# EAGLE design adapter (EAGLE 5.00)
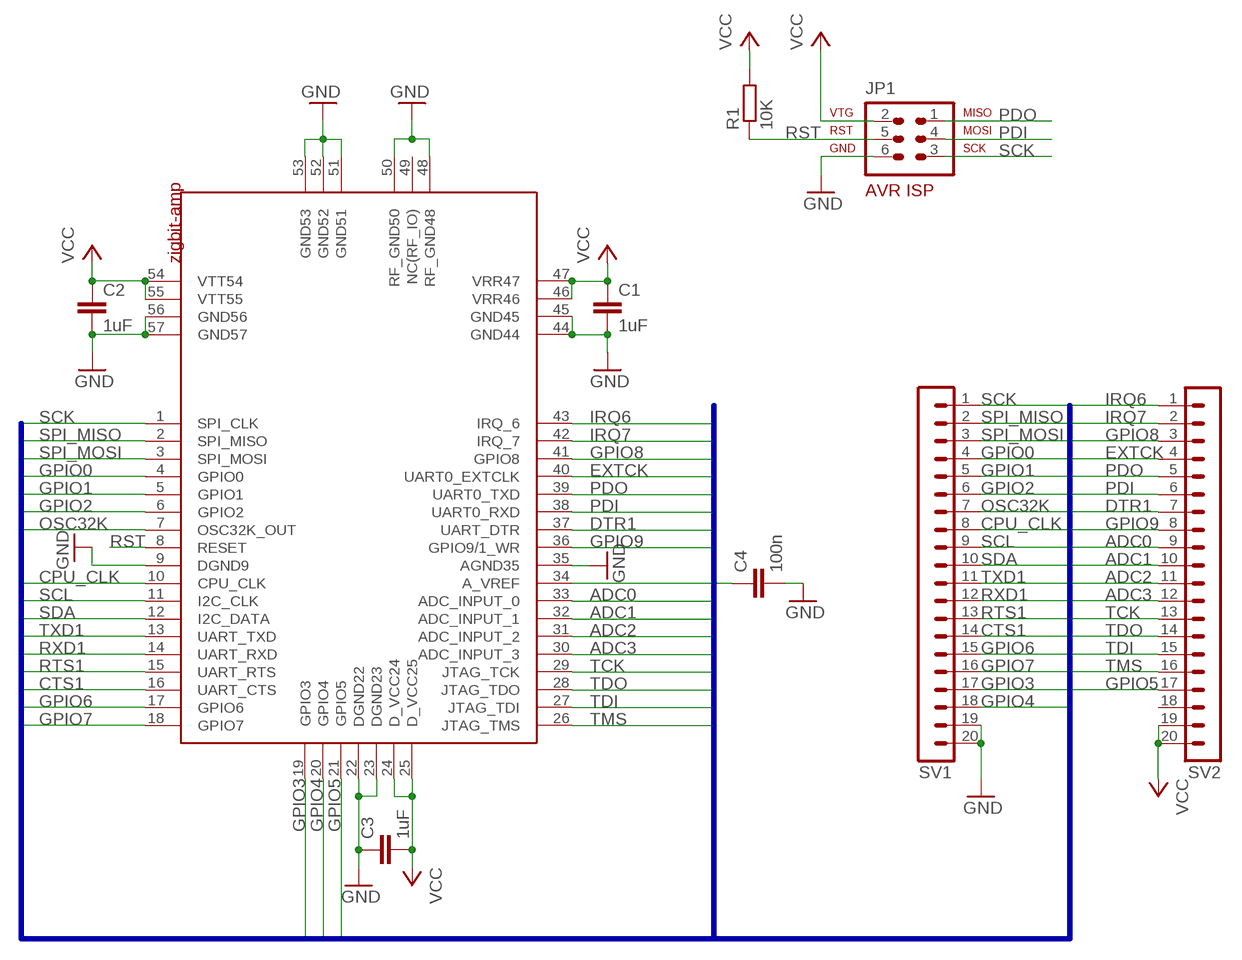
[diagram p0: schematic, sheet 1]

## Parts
C1  1uF  C-EUC1206  [C1206]
C2  1uF  C-EUC1206  [C1206]
C3  1uF  C-EUC1206  [C1206]
C4  100n  C-EUC0603  [C0603]
JP1  AVR-ISP-6  [AVR-ISP-6]
R1  10K  R-EU_R0603  [R0603]
SV1  MA20-1L  [MA20-1L]
SV2  MA20-1L  [MA20-1L]
U$1  ZIGBIT-AMP  [BOARD]

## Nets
ADC0: SV2.9 U$1.33(ADC_INPUT_0)
ADC1: SV2.10 U$1.32(ADC_INPUT_1)
ADC2: SV2.11 U$1.31(ADC_INPUT_2)
ADC3: SV2.12 U$1.30(ADC_INPUT_3)
CPU_CLK: SV1.8 U$1.10(CPU_CLK)
CTS1: SV1.14 U$1.16(UART_CTS)
DTR1: SV2.7 U$1.37(UART_DTR)
EXTCK: SV2.4 U$1.40(UART0_EXTCLK)
GND: C1.2 C2.2 C3.1 C4.2 JP1.6 SV1.19 SV1.20 U$1.9(DGND9) U$1.22(DGND22) U$1.23(DGND23) U$1.35(AGND35) U$1.44(GND44) U$1.45(GND45) U$1.48(RF_GND48) U$1.50(RF_GND50) U$1.51(GND51) U$1.52(GND52) U$1.53(GND53) U$1.56(GND56) U$1.57(GND57)
GPIO0: SV1.4 U$1.4(GPIO0)
GPIO1: SV1.5 U$1.5(GPIO1)
GPIO2: SV1.6 U$1.6(GPIO2)
GPIO3: SV1.17 U$1.19(GPIO3)
GPIO4: SV1.18 U$1.20(GPIO4)
GPIO5: SV2.17 U$1.21(GPIO5)
GPIO6: SV1.15 U$1.17(GPIO6)
GPIO7: SV1.16 U$1.18(GPIO7)
GPIO8: SV2.3 U$1.41(GPIO8)
GPIO9: SV2.8 U$1.36(GPIO9/1_WR)
IRQ6: SV2.1 U$1.43(IRQ_6)
IRQ7: SV2.2 U$1.42(IRQ_7)
N$7: C4.1 U$1.34(A_VREF)
OSC32K: SV1.7 U$1.7(OSC32K_OUT)
PDI: JP1.4 SV2.6 U$1.38(UART0_RXD)
PDO: JP1.1 SV2.5 U$1.39(UART0_TXD)
RST: JP1.5 R1.1 U$1.8(RESET)
RTS1: SV1.13 U$1.15(UART_RTS)
RXD1: SV1.12 U$1.14(UART_RXD)
SCK: JP1.3 SV1.1 U$1.1(SPI_CLK)
SCL: SV1.9 U$1.11(I2C_CLK)
SDA: SV1.10 U$1.12(I2C_DATA)
SPI_MISO: SV1.2 U$1.2(SPI_MISO)
SPI_MOSI: SV1.3 U$1.3(SPI_MOSI)
TCK: SV2.13 U$1.29(JTAG_TCK)
TDI: SV2.15 U$1.27(JTAG_TDI)
TDO: SV2.14 U$1.28(JTAG_TDO)
TMS: SV2.16 U$1.26(JTAG_TMS)
TXD1: SV1.11 U$1.13(UART_TXD)
VCC: C1.1 C2.1 C3.2 JP1.2 R1.2 SV2.19 SV2.20 U$1.24(D_VCC24) U$1.25(D_VCC25) U$1.46(VRR46) U$1.47(VRR47) U$1.54(VTT54) U$1.55(VTT55)
Unconnected: SV2.18 U$1.49(NC(RF_IO))

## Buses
SCK,SPI_MISO,SPI_MOSI,GPIO0,GPIO1,GPIO2,GPIO3,GPIO4,GPIO5,GPIO6,GPIO7,GPIO8,OSC32K,CPU_CLK,SCL,SDA,TXD1,RXD1,RTS1,CTS1,TMS,TDO,TDI,TCK,ADC3,ADC2,ADC1,ADC0,GPIO9,DTR1,MISO,MOSI,EXTCK,IRQ6,IRQ7

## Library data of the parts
C1-C4 = rcl:C-EU: CAPACITOR, European symbol
JP1 = dan:AVR-ISP-6: AVR ISP-6 Serial Programming Header
R1 = rcl:R-EU_: RESISTOR, European symbol
SV1 SV2 = con-lstb:MA20-1L: PIN HEADER
U$1 = zigbit:ZIGBIT-AMP: ZigBitTM Amp OEM Modules - ZDM-A1281-PN/PN0 (MNZB-A24-UFL/U0)

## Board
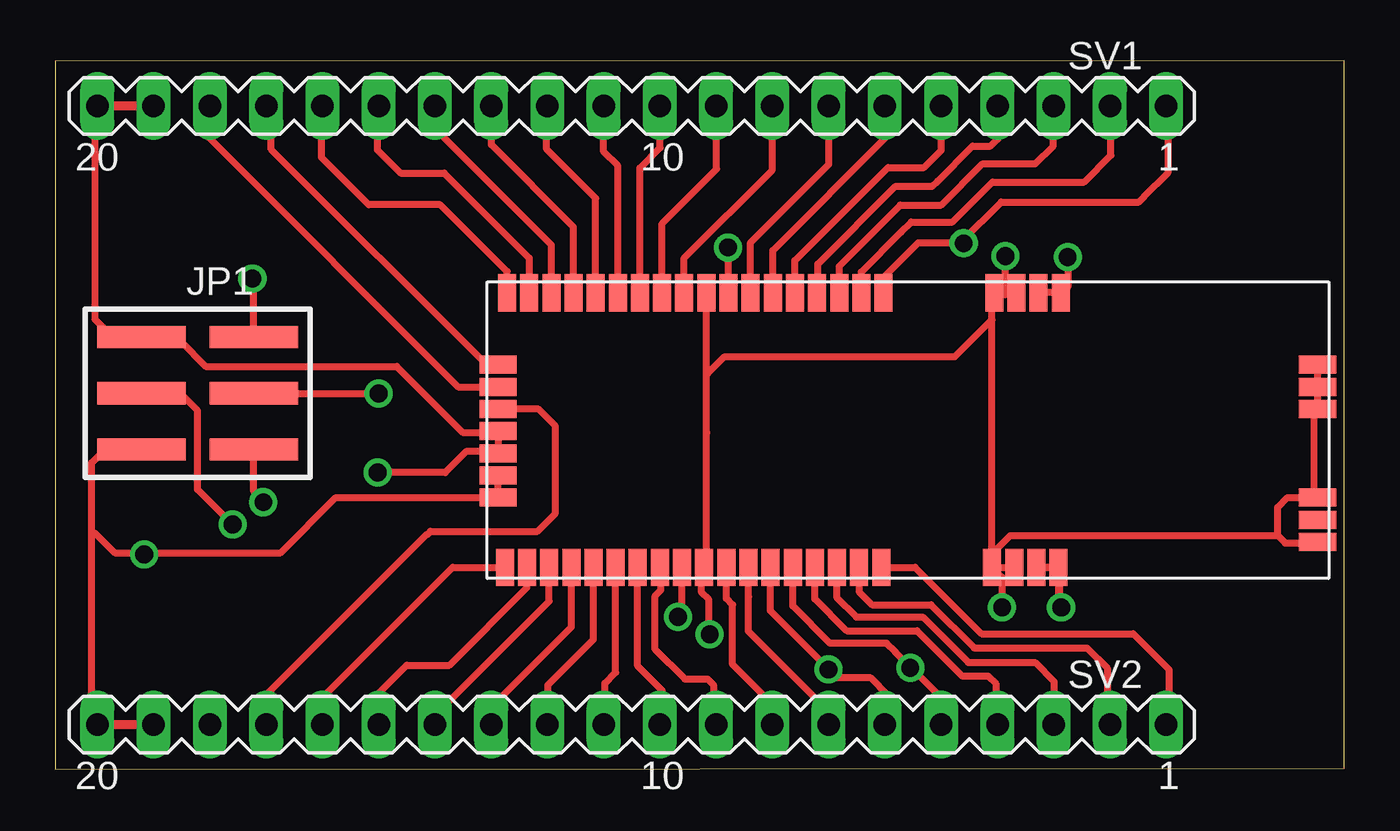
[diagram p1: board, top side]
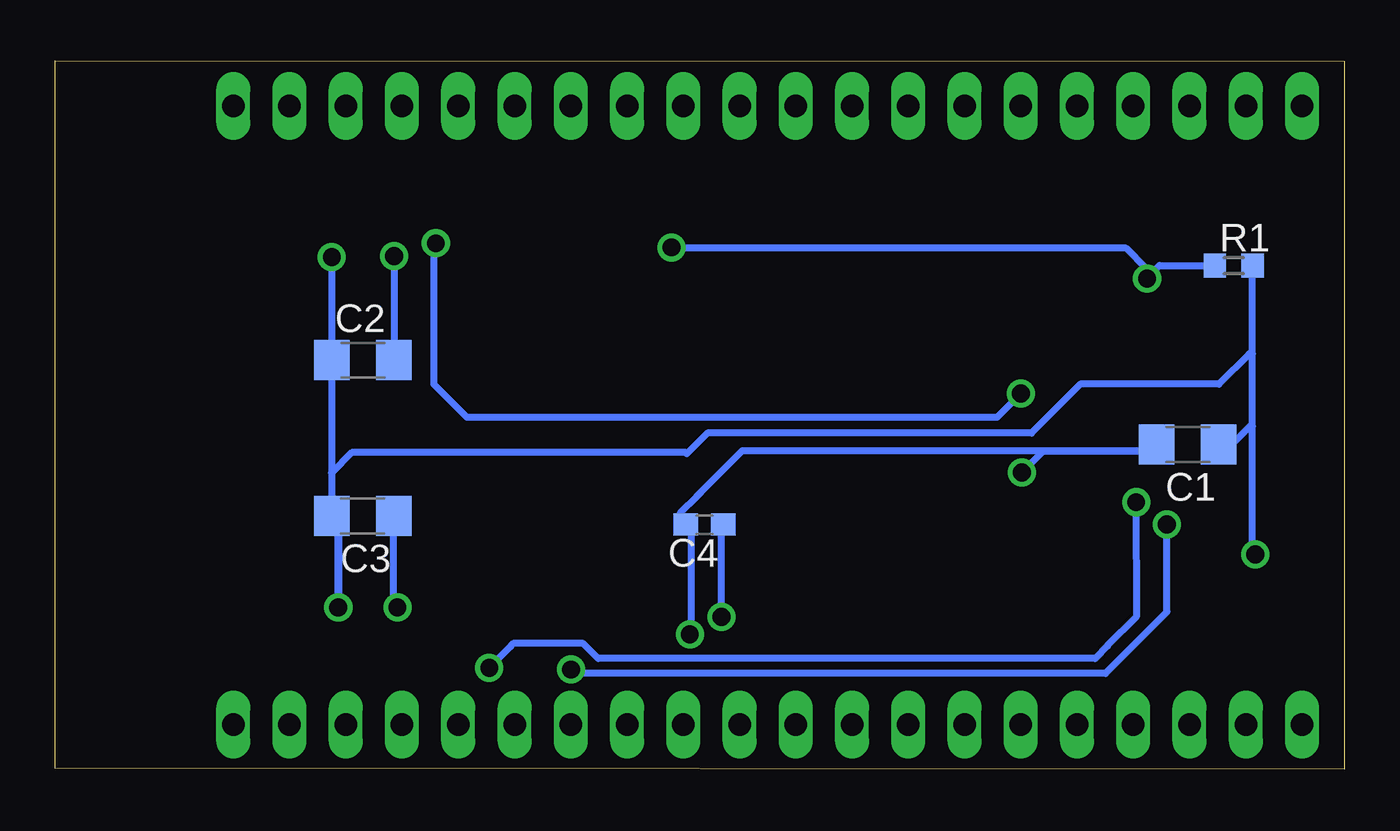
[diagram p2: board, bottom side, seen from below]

Size 58.2 x 32 mm. Coordinates in mm from the lower left corner, seen from the top.
Outline: 0,0 58.2,0.04 58.2,32 0,31.96 0,0
Copper layers (1*16): Top 0.035mm / dielectric 1.5mm / Bottom 0.035mm
Design rules "default": minimum track width 10mil, minimum drill 24mil, track to track 8mil, track to pad 8mil, pad to pad 8mil, via to via 8mil, smd to smd 8mil, copper to edge 40mil, drill to drill 8mil, minimum pad ring 10mil, minimum via ring 8mil, stop-mask expansion 4mil, vias tented up to drill 0mil, thermal gap 10mil

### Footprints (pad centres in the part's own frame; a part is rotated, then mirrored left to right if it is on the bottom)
C1206 = smd 1.6 x 1.8: 1 -1.4,0; 2 1.4,0
C0603 = smd 1.1 x 1: 1 -0.85,0; 2 0.85,0
AVR-ISP-6 = smd 1 x 4: 1 -2.54,-2.54; 2 -2.54,2.54; 3 0,-2.54; 4 0,2.54; 5 2.54,-2.54; 6 2.54,2.54
R0603 = smd 1 x 1.1: 1 -0.85,0; 2 0.85,0
MA20-1L = drill 1.016 long: 1 24.13,0; 2 21.59,0; 3 19.05,0; 4 16.51,0; 5 13.97,0; 6 11.43,0; 7 8.89,0; 8 6.35,0; 9 3.81,0; 10 1.27,0; 11 -1.27,0; 12 -3.81,0; 13 -6.35,0; 14 -8.89,0; 15 -11.43,0; 16 -13.97,0; 17 -16.51,0; 18 -19.05,0; 19 -21.59,0; 20 -24.13,0
BOARD = smd 0.813 x 1.676: 1 17.9,-0.5; 2 16.9,-0.5; 3 15.9,-0.5; 4 14.9,-0.5; 5 13.9,-0.5; 6 12.9,-0.5; 7 11.9,-0.5; 8 10.9,-0.5; 9 9.9,-0.5; 10 8.9,-0.5; 11 7.9,-0.5; 12 6.9,-0.5; 13 5.9,-0.5; 14 4.9,-0.5; 15 3.9,-0.5; 16 2.9,-0.5; 17 1.9,-0.5; 18 0.9,-0.5; 26 0.8,-12.9; 27 1.8,-12.9; 28 2.8,-12.9; 29 3.8,-12.9; 30 4.8,-12.9; 31 5.8,-12.9; 32 6.8,-12.9; 33 7.8,-12.9; 34 8.8,-12.9; 35 9.8,-12.9; 36 10.8,-12.9; 37 11.8,-12.9; 38 12.8,-12.9; 39 13.8,-12.9; 40 14.8,-12.9; 41 15.8,-12.9; 42 16.8,-12.9; 43 17.8,-12.9; 44 22.8,-12.9; 45 23.8,-12.9; 46 24.8,-12.9; 47 25.8,-12.9; 54 25.9,-0.5; 55 24.9,-0.5; 56 23.9,-0.5; 57 22.9,-0.5 | smd 1.676 x 0.813: 19 0.5,-3.75; 20 0.5,-4.75; 21 0.5,-5.75; 22 0.5,-6.75; 23 0.5,-7.75; 24 0.5,-8.75; 25 0.5,-9.75; 48 37.5,-11.75; 49 37.5,-10.75; 50 37.5,-9.75; 51 37.5,-5.75; 52 37.5,-4.75; 53 37.5,-3.75

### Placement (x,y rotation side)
C1  7.06,14.66 180 bottom
C2  44.3,18.47 0 bottom
C3  44.32,11.43 180 bottom
C4  28.89,11.05 180 bottom
JP1  6.42,16.98 90 top
R1  4.99,22.74 0 bottom
SV1  26.03,29.95 0 top
SV2  26.03,2.01 0 top
U$1  19.5,22.01 0 top

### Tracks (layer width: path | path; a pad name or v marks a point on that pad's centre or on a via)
ADC0
  Top 0.305: SV2.9 29.84,2.4 29.86,2.42 29.73,2.55 29.73,3.77 29.74,3.78 29.45,4.07 28.42,4.07 27.09,5.4 27.09,7.82 27.34,8.08 27.34,8.99 27.3,9.04 U$1.33
ADC1
  Top 0.305: U$1.32 26.3,4.65 27.41,3.54 27.41,2.13 SV2.10
ADC2
  Top 0.305: U$1.31 25.3,4.36 24.81,3.88 24.81,2.18 24.76,2.13 SV2.11
ADC3
  Top 0.305: U$1.30 24.3,5.86 22.24,3.8 22.24,2.26 22.11,2.13 SV2.12
CPU_CLK
  Top 0.305: U$1.10 28.4,23.08 32.38,27.06 32.38,30.09 | 32.38,30.09 SV1.8 | 32.38,30.09 32.22,30.24
CTS1
  Top 0.305: U$1.16 22.4,23.67 17.32,28.74 17.32,29.99 17.14,30.17 | 17.14,30.17 17.12,30.2 | 17.14,30.17 SV1.14
DTR1
  Top 0.305: 31.3,7.79 U$1.37 | 31.3,7.79 31.3,7.75 | SV2.7 34.92,2.03 34.95,2.06 34.92,2.1 34.92,2.6 31.29,6.23 31.29,7.77 31.31,7.79 31.3,7.79
EXTCK
  Top 0.305: U$1.40 34.3,7.68 35.73,6.25 38.91,6.25 40.95,4.21 42.12,4.21 42.46,3.86 42.46,2.33 42.57,2.22 42.54,2.19 SV2.4
GND  (via drill 0.8 pad 1.27)
  Top 0.305: SV1.19 1.85,29.95 1.8,30.01 1.8,20.31 2.72,19.38 3.93,19.38 | 3.93,19.38 3.88,19.43 JP1.6 | 3.93,19.38 3.97,19.34 5.64,19.34 6.8,18.19 15.41,18.19 18.39,15.21 19.77,15.21 19.83,15.14 19.96,15.26 U$1.22 U$1.23 | U$1.23 20.1,14.17 | U$1.23 | U$1.52 57,17.04 56.94,16.98 | U$1.52 U$1.53 | 57,16.14 U$1.51 | 57,16.14 U$1.52 | 57,16.14 56.84,15.98 56.84,12.4 56.78,12.34 56.86,12.26 U$1.50 55.64,12.26 55.2,11.82 55.2,10.54 | 55.2,10.54 55.53,10.21 56.6,10.21 56.64,10.18 56.72,10.26 U$1.48 | 42.3,9.36 42.27,9.38 | U$1.44 42.3,9.36 | U$1.45 42.55,9.11 42.3,9.36 | 42.29,21.51 U$1.57 | U$1.57 42.9,21.51 | 42.9,21.51 U$1.56 | 42.29,21.51 42.26,21.54 | 29.19,9.54 29.3,9.43 U$1.35 | 29.4,15.24 29.4,9.75 29.19,9.54 | 29.4,15.24 29.4,17.86 | 29.4,17.86 U$1.9 | 29.4,15.24 29.41,15.16 | 42.29,21.51 42.29,20.3 40.62,18.63 30.23,18.63 29.45,17.86 29.4,17.86 | 55.2,10.54 43.13,10.54 42.27,9.69 | U$1.44 42.35,9.16 42.27,9.24 42.27,9.69 | U$1.57 42.4,21.32 42.27,21.2 42.27,9.69 | 29.19,9.54 29.19,7.97 29.5,7.65 29.5,6.17 29.57,6.1 v29.55,6.08 | U$1.44 42.75,8.66 v42.75,7.3 | 42.9,21.51 42.9,21.42 | 42.9,21.51 v42.9,23.17 | v14.56,13.39 17.6,13.39 18.54,14.33 19.92,14.33 U$1.23 | U$1.23 20.01,14.24
  Top 0.406: SV1.20 2.12,29.95 2.13,29.94 2.14,29.95 SV1.19
  Bottom 0.305: v29.55,6.08 29.55,6.06 29.52,6.03 29.49,6.06 29.49,10.88 29.7,11.08 C4.2 29.86,11.05 29.91,10.99 29.98,11.06 29.98,11.56 29.22,12.32 | C3.1 42.92,7.38 v42.75,7.3 | C2.2 v42.9,23.16 v42.9,23.17 | 29.22,12.32 29.05,12.49 | 29.22,12.32 29.23,12.32 27.19,14.37 8.88,14.37 8.59,14.66 C1.2 8.89,14.66 9.21,14.33 9.21,14.36 13.59,14.36 v14.56,13.39
GPIO0
  Top 0.305: 42.69,30.22 42.54,30.07 SV1.4 42.54,28.45 42.23,28.14 41.42,28.14 39.85,26.57 39.84,26.57 39.6,26.32 37.94,26.32 34.43,22.81 34.43,21.75 34.26,21.57 34.33,21.51 U$1.4
GPIO1
  Top 0.305: U$1.5 33.4,22.97 37.6,27.17 39.22,27.17 40,27.95 40,30.35 39.89,30.46 39.89,30.07 40.02,29.95 | 40.02,29.95 40.15,29.81 | 40.02,29.95 SV1.5
GPIO2
  Top 0.305: U$1.6 32.4,23.42 37.55,28.58 37.55,29.88 37.46,29.97 | 37.46,29.97 37.42,30.01 | 37.46,29.97 SV1.6
GPIO3
  Top 0.305: U$1.19 19.47,18.26 9.75,27.98 9.75,29.73 SV1.17
GPIO4
  Top 0.305: U$1.20 18.19,17.26 6.9,28.55 6.9,29.93 6.92,29.95 SV1.18
GPIO5
  Top 0.305: SV2.17 9.52,3.35 16.75,10.58 16.78,10.58 16.94,10.73 21.76,10.73 22.58,11.55 22.58,15.48 21.81,16.25 20.13,16.25 20.02,16.37 20,16.35 U$1.21
GPIO6
  Top 0.305: U$1.17 21.4,23.08 17.56,26.92 15.58,26.92 14.54,27.96 14.54,29.81 14.6,29.87 SV1.15
GPIO7
  Top 0.305: U$1.18 20.4,22.47 17.38,25.49 14.15,25.49 12.02,27.62 12.02,30.02 | 12.02,30.02 12.06,29.98 SV1.16 | 12.02,30.02 11.92,30.12
GPIO8
  Top 0.305: U$1.41 35.3,7.73 36.16,6.86 39.17,6.86 41.22,4.81 44.24,4.81 45.1,3.95 45.1,2.74 45.26,2.58 45.26,2.33 45.08,2.15 SV2.3
GPIO9
  Top 0.305: SV2.8 32.41,2.01 32.48,2.08 32.48,2.82 32.48,2.81 | U$1.36 30.3,7.7 30.58,7.42 30.58,4.72 32.48,2.81 | 32.48,2.81
IRQ6
  Top 0.305: U$1.43 38.82,9.11 41.82,6.11 48.67,6.11 50.29,4.5 50.29,1.88 | 50.29,1.88 SV2.1 | 50.29,1.88 50.4,1.76
IRQ7
  Top 0.305: U$1.42 36.3,8 36.88,7.42 39.55,7.42 41.5,5.47 46.59,5.47 47.5,4.56 47.5,2.49 47.78,2.21 47.62,2.06 SV2.2
N$7  (via drill 0.8 pad 1.27)
  Top 0.305: U$1.34 28.3,7.05 v28.12,6.87
  Bottom 0.305: C4.1 28.12,10.97 v28.12,6.87
OSC32K
  Top 0.305: U$1.7 31.4,23.79 34.93,27.32 34.93,30.05 34.92,30.06 | 34.92,30.06 34.82,30.16 | 34.92,30.06 SV1.7
PDI  (via drill 0.8 pad 1.27)
  Top 0.305: SV2.6 37.34,1.9 | SV2.6 | SV2.6 37.57,2.13 37.57,3.36 36.8,4.13 35.3,4.13 35.24,4.19 | 35.24,4.19 32.28,7.15 32.28,9.01 32.38,9.11 | 32.38,9.11 32.39,9.12 | 32.38,9.11 U$1.38 | JP1.4 5.63,16.98 6.43,16.18 6.43,12.63 v8,11.05 | 35.24,4.19 35.22,4.17 34.91,4.47 v34.91,4.5 | 35.24,4.19
  Bottom 0.305: v8,11.05 8,7.1 10.27,4.84 10.27,4.83 10.78,4.32 34.8,4.32 34.98,4.5 | 34.57,4.84 v34.91,4.5 34.98,4.5 | 34.98,4.5 35,4.52
PDO  (via drill 0.8 pad 1.27)
  Top 0.305: 38.3,4.91 37.94,5.27 | 38.3,4.91 39.83,3.39 39.83,2.28 40.08,2.03 40.06,2.01 SV2.5 | 38.3,4.91 38.3,4.92 38.61,4.61 v38.61,4.58 38.61,4.59 38.2,5 | U$1.39 33.3,7.36 34.98,5.68 37.54,5.68 37.93,5.29 37.93,5.27 38.2,5 | 38.2,5 | v9.39,12.05 9.42,12.05 9.44,12.06 8.96,12.54 JP1.1
  Bottom 0.305: v9.39,12.05 9.37,6.9 10.69,5.58 10.69,5.56 11.24,5 33.69,5 34.36,5.67 37.52,5.67 37.64,5.56 37.64,5.54 38.61,4.57 | 37.6,5.58 v38.61,4.58 38.61,4.57 | 38.61,4.57 38.62,4.55
RST  (via drill 0.8 pad 1.27)
  Top 0.305: JP1.5 8.96,22.09 v8.9,22.15 | U$1.8 30.36,21.51 30.34,21.53 30.37,21.56 v30.37,23.56
  Bottom 0.305: v30.37,23.56 30.34,23.53 9.84,23.53 8.9,22.59 v8.9,22.15 8.92,22.17 8.34,22.74 R1.1
RTS1
  Top 0.305: U$1.15 23.4,24.49 19.69,28.2 19.69,29.65 19.77,29.73 19.68,29.82 SV1.13
RXD1
  Top 0.305: U$1.14 24.4,25.78 22.19,27.99 22.19,29.76 22.29,29.86 22.22,29.93 SV1.12
SCK  (via drill 0.8 pad 1.27)
  Top 0.305: SV1.1 50.24,29.95 50.25,29.94 50.25,26.94 49.16,25.85 49.16,25.84 48.93,25.61 42.71,25.61 40.92,23.82 | U$1.1 37.4,22.21 38.95,23.76 40.86,23.76 40.92,23.82 | 40.92,23.82 40.93,23.82 v41,23.75 v41.01,23.75 | JP1.3 8.96,17 8.98,17.02 9.04,16.96 v14.6,16.96
  Bottom 0.305: 40.99,23.72 v41.01,23.75 41.08,23.75 41.1,23.77 41.1,17.37 39.61,15.88 15.68,15.88 v14.6,16.96
SCL
  Top 0.305: U$1.11 27.4,24.64 29.86,27.1 29.86,29.98 29.84,30.01 | 29.84,30.01 29.75,30.09 | 29.84,30.01 SV1.9
SDA
  Top 0.305: U$1.12 26.4,27.15 27.3,28.06 SV1.10 27.31,29.95 | 27.31,29.95 27.43,30.07 | 27.31,29.95 SV1.10
SPI_MISO
  Top 0.305: U$1.2 36.4,22.46 38.18,24.24 38.19,24.24 38.65,24.71 40.51,24.71 42.32,26.51 46.46,26.51 47.66,27.72 47.65,27.73 47.65,29.81 48.06,30.22 48,30.22 47.73,29.95 SV1.2
SPI_MOSI
  Top 0.305: U$1.3 35.4,22.71 37.88,25.2 38.16,25.48 40.01,25.48 41.87,27.34 44.25,27.34 45.06,28.14 45.06,29.98 SV1.3 45.05,29.92
TCK
  Top 0.305: U$1.29 23.3,6.42 19.66,2.78 19.66,1.98 | 19.66,1.98 19.68,1.99 SV2.13 | 19.66,1.98 19.56,1.87
TDI
  Top 0.305: U$1.27 21.3,8.2 17.79,4.69 15.86,4.69 14.52,3.35 14.52,1.98 14.2,1.65 14.35,1.65 14.6,1.91 SV2.15
TDO
  Top 0.305: SV2.14 17.14,2.32 17.09,2.37 22.3,7.57 U$1.28
TMS
  Top 0.305: U$1.26 17.94,9.11 12.03,3.19 12.03,2 | 12.03,2 12.04,2.01 SV2.16 | 12.03,2 11.96,1.94
TXD1
  Top 0.305: U$1.13 25.4,27.25 24.76,27.88 24.76,29.91 24.72,29.95 | 24.72,29.95 24.68,29.99 | 24.72,29.95 SV1.11
VCC  (via drill 0.8 pad 1.27)
  Top 0.305: JP1.2 2.24,14.43 1.64,13.83 1.64,10.65 | 2,1.92 SV2.20 | SV2.20 | 1.64,10.65 1.64,2.28 SV2.20 | U$1.24 20,12.5 19.93,12.44 20,12.37 U$1.25 12.66,12.26 10.16,9.77 3.84,9.77 | 44.3,8.88 44.3,8.87 | 44.3,8.88 U$1.46 45.32,9.11 45.35,9.07 45.35,7.37 v45.41,7.31 | 44.3,8.88 44.53,9.11 U$1.47 45.3,7.43 v45.43,7.3 | U$1.55 44.4,21.61 44.54,21.74 44.77,21.51 U$1.54 45.48,21.51 45.72,21.75 v45.72,23.12 | 1.64,10.65 1.8,10.65 2.68,9.77 3.84,9.77 | 3.84,9.77 3.84,9.69 v4.01,9.69
  Top 0.406: SV2.19 SV2.20 1.75,2.01 1.66,1.92
  Bottom 0.305: 4.14,15.47 4.14,9.82 v4.01,9.69 | 4.14,15.47 4.14,18.75 | 4.14,18.75 R1.2 | 4.14,15.47 4.25,15.47 5.07,14.66 C1.1 | v45.43,7.3 45.43,11.32 45.71,11.6 45.72,11.59 C3.2 45.75,11.43 | v45.72,23.12 45.7,23.11 C2.1 45.7,11.48 45.75,11.43 | 45.75,11.43 45.77,11.42 | v45.41,7.31 45.41,11.95 45.72,12.26 45.72,13.38 44.81,14.29 29.72,14.29 29.68,14.25 28.75,15.18 14.12,15.18 11.91,17.38 5.66,17.38 4.29,18.75 4.14,18.75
